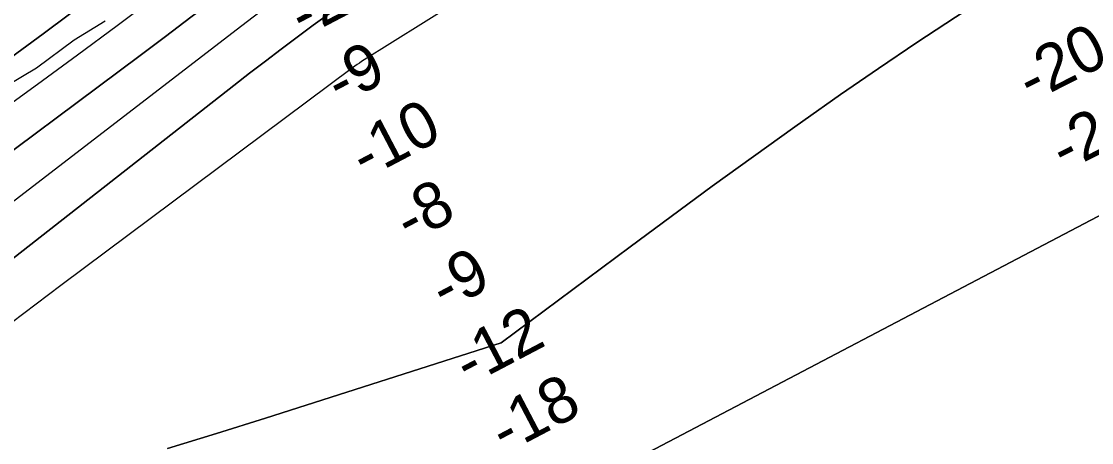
# Model space of a CAD drawing. Extents: x 3245246 to 3283090, y 806824 to 832173.
# Drawn here: x 3251976 to 3253367, y 816848 to 817394 of the extents above; entities that cross this region are included whole.
import ezdxf

# ---------------------------------------------------------------- set-up
doc = ezdxf.new("R2010")
doc.units = 0
for name, color, linetype in [('V-RIVR-EDGE', 7, 'Continuous'), ('V-RIVR-RANG', 7, 'Continuous'), ('V-TOPO-DPTH', 7, 'Continuous'), ('V-TOPO-MINR', 7, 'Continuous'), ('V-TOPO-WATR', 7, 'Continuous')]:
    doc.layers.add(name, color=color, linetype=linetype)

msp = doc.modelspace()

# ---------------------------------------------------------------- linework, layer by layer
at = {"layer": 'V-RIVR-EDGE'}
msp.add_lwpolyline([(3252085.2, 817394.5), (3252045.1, 817369.9), (3251995.9, 817333.5), (3251957.6, 817310.5)], dxfattribs=at)
at = {"layer": 'V-TOPO-DPTH'}
for points in [[(3251934.2, 817326.6), (3252004.9, 817378.1), (3252074.8, 817430.6), (3252144.2, 817483.8), (3252213.3, 817537.5), (3252282.4, 817591.1), (3252351.5, 817644.7), (3252420.7, 817698.2), (3252434.7, 817708.9), (3252510.5, 817768.1), (3252585.9, 817827.9), (3252660.7, 817888.6), (3252735, 817949.7), (3252806.6, 818009.3), (3252879.3, 818069.2), (3252952.5, 818128.6), (3253026.3, 818187.3), (3253100.6, 818245.4), (3253175.5, 818302.5), (3253251, 818358.9), (3253327.3, 818414.2), (3253404.2, 818468.8)], [(3251860.3, 817004.6), (3252252.3, 817310.9), (3252272.7, 817326.8), (3252293.3, 817342.6), (3252313.9, 817358.2), (3252334.6, 817373.8), (3252355.5, 817389.1), (3252376.5, 817404.2), (3252397.8, 817419), (3252419.2, 817433.6), (3252433.2, 817443), (3252461.7, 817462.2), (3252490.1, 817481.5), (3252518.5, 817500.9), (3252546.7, 817520.4), (3253074.7, 817886.5), (3253744.9, 818382.9)], [(3253744.9, 818382.9), (3253074.7, 817886.5), (3252546.7, 817520.4), (3252518.5, 817500.9), (3252490.1, 817481.5), (3252461.7, 817462.2), (3252433.2, 817443), (3252419.2, 817433.6), (3252397.8, 817419), (3252376.5, 817404.2), (3252355.5, 817389.1), (3252334.6, 817373.8), (3252313.9, 817358.2), (3252293.3, 817342.6), (3252272.7, 817326.8), (3252252.3, 817310.9), (3251860.3, 817004.6)], [(3251886.6, 817168), (3252130.5, 817349.9), (3252163.6, 817374.7), (3252196.6, 817399.5), (3252229.6, 817424.4), (3252262.5, 817449.3), (3252295.4, 817474.2), (3252328.5, 817499), (3252361.7, 817523.5), (3252395.1, 817547.8), (3252720.4, 817783.2), (3252770, 817819.4), (3252819.4, 817855.9), (3252868.5, 817892.8), (3252917.4, 817929.9), (3252966.2, 817967.3), (3253015, 818004.5), (3253063.9, 818041.7), (3253112.8, 818078.8), (3253396.3, 818293.4)], [(3253396.3, 818293.4), (3253112.8, 818078.8), (3253063.9, 818041.7), (3253015, 818004.5), (3252966.2, 817967.3), (3252917.4, 817929.9), (3252868.5, 817892.8), (3252819.4, 817855.9), (3252770, 817819.4), (3252720.4, 817783.2), (3252395.1, 817547.8), (3252361.7, 817523.5), (3252328.5, 817499), (3252295.4, 817474.2), (3252262.5, 817449.3), (3252229.6, 817424.4), (3252196.6, 817399.5), (3252163.6, 817374.7), (3252130.5, 817349.9), (3251886.6, 817168)], [(3253445, 817533.6), (3253314.4, 817475.6), (3253302.4, 817469.9), (3253290.7, 817463.9), (3253279.2, 817457.3), (3253267.9, 817450.4), (3253189.6, 817399.5), (3253139.6, 817366.6), (3253089.8, 817333.2), (3253040.5, 817299.2), (3252991.4, 817264.7), (3252981.2, 817257.5), (3252927.5, 817218.9), (3252873.8, 817180.2), (3252820.5, 817141), (3252767.3, 817101.6), (3252599.8, 816976.8), (3252293.5, 816879.2), (3252230, 816859.2), (3252166.4, 816839.7)], [(3252166.4, 816839.7), (3252230, 816859.2), (3252293.5, 816879.2), (3252599.8, 816976.8), (3252767.3, 817101.6), (3252820.5, 817141), (3252873.8, 817180.2), (3252927.5, 817218.9), (3252981.2, 817257.5), (3252991.4, 817264.7), (3253040.5, 817299.2), (3253089.8, 817333.2), (3253139.6, 817366.6), (3253189.6, 817399.5), (3253267.9, 817450.4), (3253279.2, 817457.3), (3253290.7, 817463.9), (3253302.4, 817469.9), (3253314.4, 817475.6), (3253445, 817533.6)], [(3253426.6, 817168.1), (3252704.2, 816789.3)], [(3252704.2, 816789.3), (3253426.6, 817168.1)]]:
    msp.add_lwpolyline(points, dxfattribs=at)
at = {"layer": 'V-TOPO-MINR'}
for points in [[(3253404.2, 818468.8), (3253327.3, 818414.2), (3253251, 818358.9), (3253175.5, 818302.5), (3253100.6, 818245.4), (3253026.3, 818187.3), (3252952.5, 818128.6), (3252879.3, 818069.2), (3252806.6, 818009.3), (3252735, 817949.7), (3252660.7, 817888.6), (3252585.9, 817827.9), (3252510.5, 817768.1), (3252434.7, 817708.9), (3252420.7, 817698.2), (3252351.5, 817644.7), (3252282.4, 817591.1), (3252213.3, 817537.5), (3252144.2, 817483.8), (3252074.8, 817430.6), (3252004.9, 817378.1), (3251934.2, 817326.6)], [(3253744.9, 818382.9), (3253074.7, 817886.5), (3252546.7, 817520.4), (3252518.5, 817500.9), (3252490.1, 817481.5), (3252461.7, 817462.2), (3252433.2, 817443), (3252419.2, 817433.6), (3252397.8, 817419), (3252376.5, 817404.2), (3252355.5, 817389.1), (3252334.6, 817373.8), (3252313.9, 817358.2), (3252293.3, 817342.6), (3252272.7, 817326.8), (3252252.3, 817310.9), (3251860.3, 817004.6)], [(3253381.4, 818368.4), (3253300.5, 818308.1), (3253220, 818247.3), (3253127.3, 818176.3), (3253055.6, 818121.1), (3252984.2, 818065.7), (3252913.2, 818009.7), (3252842.3, 817953.5), (3252771.4, 817897.4), (3252700.2, 817841.7), (3252628.4, 817786.8), (3252556.2, 817732.3), (3252408.5, 817621.9), (3252357.1, 817583.2), (3252305.7, 817544.5), (3252254.6, 817505.5), (3252203.5, 817466.3), (3252152.3, 817427.3), (3252100.9, 817388.6), (3252049.2, 817350.3), (3251997.3, 817312.4), (3251903.4, 817244.4)], [(3253571.3, 818338.6), (3253095.4, 817982.3), (3253070.3, 817963.6), (3253045.1, 817944.9), (3253019.9, 817926.2), (3252994.7, 817907.6), (3252969.4, 817889.1), (3252944, 817870.8), (3252918.4, 817852.6), (3252892.8, 817834.5), (3252380.5, 817475.9), (3252365.5, 817465.3), (3252350.6, 817454.6), (3252335.8, 817443.7), (3252321.2, 817432.8), (3252306.5, 817421.7), (3252291.9, 817410.6), (3252277.4, 817399.5), (3252262.8, 817388.4), (3251872.1, 817088.4)], [(3253536.8, 817767.6), (3253291.9, 817731.2), (3253228.5, 817720), (3253165.7, 817706.6), (3253103.7, 817689.8), (3253042.3, 817670.8), (3252981.8, 817648.7), (3252922.1, 817624.7), (3252863.6, 817598.1), (3252805.9, 817569.7), (3252791.2, 817562.1), (3252727.2, 817527.7), (3252663.7, 817492.4), (3252601.1, 817455.5), (3252539, 817417.6), (3252418.4, 817342.1), (3252415.4, 817340.1), (3252412.5, 817338.2), (3252409.5, 817336.1), (3252406.7, 817334), (3252027.8, 817051.4), (3251995.6, 817027.3), (3251963.4, 817003.1)], [(3253445, 817533.6), (3253314.4, 817475.6), (3253302.4, 817469.9), (3253290.7, 817463.9), (3253279.2, 817457.3), (3253267.9, 817450.4), (3253189.6, 817399.5), (3253139.6, 817366.6), (3253089.8, 817333.2), (3253040.5, 817299.2), (3252991.4, 817264.7), (3252981.2, 817257.5), (3252927.5, 817218.9), (3252873.8, 817180.2), (3252820.5, 817141), (3252767.3, 817101.6), (3252599.8, 816976.8), (3252293.5, 816879.2), (3252230, 816859.2), (3252166.4, 816839.7)], [(3253426.6, 817168.1), (3252704.2, 816789.3)]]:
    msp.add_lwpolyline(points, dxfattribs=at)
at = {"layer": 'V-TOPO-WATR'}
msp.add_lwpolyline([(3253396.3, 818293.4), (3253112.8, 818078.8), (3253063.9, 818041.7), (3253015, 818004.5), (3252966.2, 817967.3), (3252917.4, 817929.9), (3252868.5, 817892.8), (3252819.4, 817855.9), (3252770, 817819.4), (3252720.4, 817783.2), (3252395.1, 817547.8), (3252361.7, 817523.5), (3252328.5, 817499), (3252295.4, 817474.2), (3252262.5, 817449.3), (3252229.6, 817424.4), (3252196.6, 817399.5), (3252163.6, 817374.7), (3252130.5, 817349.9), (3251886.6, 817168)], dxfattribs=at)

# ---------------------------------------------------------------- texts
at = {"layer": 'V-RIVR-RANG'}
for s, rotation, p in [('-2', 27.7224, (3252343, 817372.8)), ('-20', 26.8489, (3253288.2, 817288.5)), ('-9', 27.7224, (3252390.6, 817284.9)), ('-22', 26.8489, (3253331.4, 817198.3)), ('-10', 27.7224, (3252423, 817188.9)), ('-8', 27.7224, (3252480.6, 817106.2)), ('-9', 27.7224, (3252526.5, 817017.4)), ('-12', 27.7224, (3252557.4, 816920.7)), ('-18', 27.7224, (3252604.3, 816832.4))]:
    msp.add_text(s, height=60, rotation=rotation, dxfattribs=at).set_placement(p)

doc.saveas('drawing.dxf')
